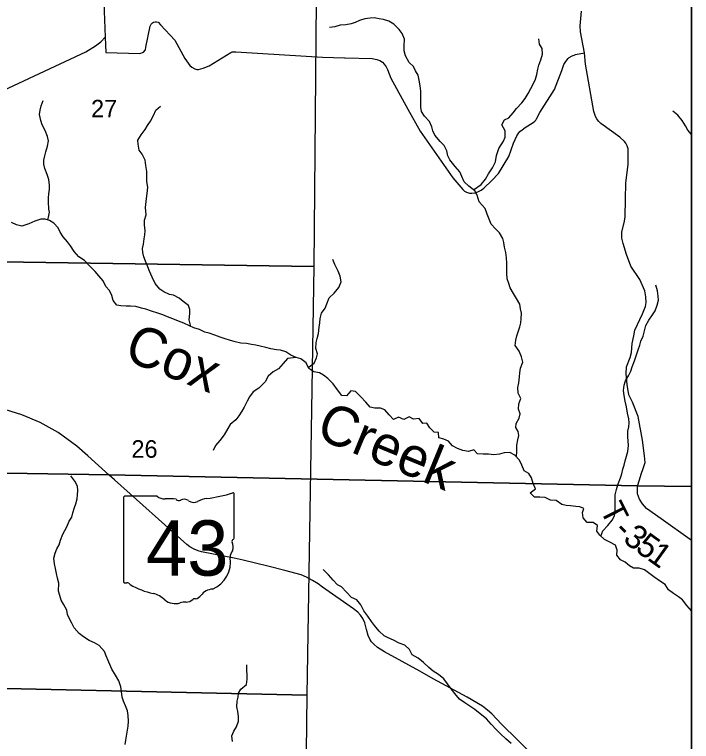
# Model space of a CAD drawing. Extents: x -3.6 to 34, y 0 to 32.8.
# Drawn here: x 1.556 to 3.17, y 29.85 to 31.583 of the extents above; entities that cross this region are included whole.
import ezdxf

# ---------------------------------------------------------------- set-up
doc = ezdxf.new("R2010")
doc.units = 0
for name, color, linetype in [('GM_X_Corporation', 7, 'Continuous'), ('GM_X_Minor_River', 7, 'Continuous'), ('GM_X_Minor_River_Text', 7, 'Continuous'), ('GM_X_Section_Text', 7, 'Continuous'), ('GM_X_State_Location', 7, 'Continuous'), ('GM_X_State_Route', 7, 'Continuous'), ('GM_X_State_Shield', 7, 'Continuous'), ('GM_X_Township_Road', 7, 'Continuous'), ('GM_X_Township_Road_Text', 7, 'Continuous'), ('SH_Data', 7, 'Continuous')]:
    doc.layers.add(name, color=color, linetype=linetype)

msp = doc.modelspace()

# ---------------------------------------------------------------- linework, layer by layer
at = {"layer": 'GM_X_Corporation'}
for points in [[(3.1705, 28.9337), (3.1705, 32.8429), (-3.6295, 32.8429), (-3.6295, 26.0429), (2.3706, 26.0429), (2.3712, 26.0804), (2.3716, 26.1248), (2.3732, 26.2253), (2.3789, 26.6097), (2.3911, 27.5117), (2.3952, 27.9336), (2.3997, 28.282), (2.4082, 28.9473), (2.5416, 28.945), (2.5837, 28.9442), (2.8343, 28.9397)], [(3.1705, 30.458), (3.1705, 32.8429), (-3.6295, 32.8429), (-3.6295, 30.6462), (-3.5736, 30.6453), (-2.8007, 30.6338), (-2.7027, 30.634), (-2.3541, 30.6318), (-0.5034, 30.5954), (-0.453, 30.5952), (-0.398, 30.5946), (0.2583, 30.5905), (0.2578, 30.5133), (0.3556, 30.5115), (0.4055, 30.5105), (1.2437, 30.4948), (1.7819, 30.4857), (3.0419, 30.4594)], [(1.2712, 32.0083), (2.2789, 31.9792), (2.27, 30.9827), (1.2573, 30.9978)], [(1.2573, 30.9978), (2.27, 30.9827), (2.2535, 29.9602), (1.2483, 29.9822)], [(2.2535, 29.9602), (2.2411, 28.9502), (1.4051, 28.9619), (1.2386, 28.9647), (1.2483, 29.9822)]]:
    msp.add_lwpolyline(points, close=True, dxfattribs=at)
msp.add_lwpolyline([(-2.8635, 26.0429), (2.3706, 26.0429), (2.3712, 26.0804), (2.3716, 26.1248), (2.3732, 26.2253), (2.3789, 26.6097), (2.3911, 27.5117), (2.3952, 27.9336), (2.3997, 28.282), (2.4082, 28.9473), (2.5416, 28.945), (2.5837, 28.9442), (2.8343, 28.9397), (3.1705, 28.9337), (3.1705, 30.458), (3.0419, 30.4594), (1.7819, 30.4857), (1.2437, 30.4948), (0.4055, 30.5105), (0.3556, 30.5115), (0.2578, 30.5133), (0.2583, 30.5905), (-0.398, 30.5946), (-0.453, 30.5952)], dxfattribs=at)
at = {"layer": 'GM_X_Minor_River'}
for points in [[(2.6645, 31.1367), (2.6593, 31.1528), (2.6538, 31.163), (2.6399, 31.1741), (2.6284, 31.1849), (2.6225, 31.1974), (2.6181, 31.2083), (2.6069, 31.221), (2.5941, 31.2367), (2.5897, 31.2469), (2.5873, 31.2583), (2.5806, 31.2714), (2.5709, 31.2811), (2.5585, 31.2961), (2.5538, 31.3059), (2.5514, 31.3157), (2.5459, 31.3282), (2.5335, 31.3412), (2.5265, 31.3521), (2.5251, 31.3627), (2.5249, 31.3779), (2.5251, 31.3908), (2.5249, 31.401), (2.5235, 31.4135), (2.5214, 31.4272), (2.5189, 31.4389), (2.5123, 31.4494), (2.5076, 31.4592), (2.4975, 31.4693), (2.4886, 31.4847), (2.4857, 31.4968), (2.4855, 31.5089), (2.4864, 31.5249), (2.4808, 31.5381), (2.4734, 31.5482), (2.4607, 31.5605), (2.4488, 31.5679), (2.4358, 31.5719), (2.4256, 31.5736), (2.4141, 31.5753), (2.4046, 31.5751), (2.3914, 31.5734), (2.3785, 31.5694), (2.3688, 31.5643), (2.3586, 31.5615), (2.3461, 31.559), (2.3328, 31.5581), (2.3203, 31.5544), (2.3074, 31.5527)], [(2.6505, 31.1656), (2.6691, 31.178), (2.6795, 31.1911), (2.6861, 31.2037), (2.6958, 31.2183), (2.7031, 31.2324), (2.7059, 31.2477), (2.711, 31.2637), (2.7224, 31.2813), (2.7264, 31.2909), (2.7262, 31.3064), (2.718, 31.3207), (2.725, 31.3322), (2.7348, 31.3369), (2.7452, 31.3488), (2.753, 31.3592), (2.7661, 31.3731), (2.7739, 31.3834), (2.7813, 31.3953), (2.7871, 31.4072), (2.7927, 31.4175), (2.7982, 31.4294), (2.8014, 31.4404), (2.8038, 31.4534), (2.8063, 31.4629), (2.8111, 31.4751), (2.815, 31.4892), (2.8144, 31.5029), (2.8081, 31.513), (2.8064, 31.5255)], [(1.6381, 31.1192), (1.6371, 31.1365), (1.6373, 31.1464), (1.6383, 31.1559), (1.6392, 31.1669), (1.6398, 31.1768), (1.6377, 31.19), (1.6341, 31.2021), (1.6285, 31.2161), (1.6261, 31.2263), (1.6263, 31.2365), (1.6288, 31.2464), (1.6309, 31.2559), (1.6352, 31.2693), (1.6369, 31.2826), (1.6352, 31.2928), (1.6293, 31.3071), (1.6222, 31.3207), (1.6186, 31.3305), (1.6161, 31.3452), (1.6171, 31.3551), (1.6196, 31.3654), (1.6243, 31.3784)], [(1.8685, 31.1231), (1.8712, 31.1449), (1.8725, 31.1571), (1.8742, 31.1716), (1.872, 31.1852), (1.8718, 31.1973), (1.872, 31.2095), (1.8695, 31.2231), (1.8678, 31.2359), (1.8603, 31.2502), (1.8537, 31.2604), (1.8508, 31.274), (1.8503, 31.2838), (1.8584, 31.2965), (1.8681, 31.3096), (1.8736, 31.3191), (1.8803, 31.3291), (1.8876, 31.3425), (1.8935, 31.3551), (1.9039, 31.3652)], [(3.1705, 31.2978), (3.162, 31.3074), (3.1565, 31.3183), (3.1487, 31.3311), (3.1379, 31.3435), (3.1263, 31.3531)], [(2.7531, 30.5281), (2.7538, 30.5434), (2.7543, 30.5563), (2.7564, 30.5696), (2.7585, 30.5795), (2.7576, 30.589), (2.7518, 30.5988), (2.7524, 30.6083), (2.7594, 30.6209), (2.7619, 30.6316), (2.7579, 30.6421), (2.7592, 30.6547), (2.7636, 30.668), (2.7573, 30.6808), (2.7567, 30.6944), (2.7589, 30.7051), (2.7602, 30.7191), (2.7615, 30.7294), (2.7629, 30.74), (2.7683, 30.7545), (2.7655, 30.7674), (2.7596, 30.781), (2.7499, 30.7945), (2.7516, 30.807), (2.7537, 30.8169), (2.7574, 30.8268), (2.7614, 30.8386), (2.7635, 30.8485), (2.7645, 30.858), (2.765, 30.8713), (2.763, 30.8815), (2.7609, 30.8925), (2.7531, 30.906), (2.7461, 30.9184), (2.7384, 30.9316), (2.7352, 30.9418), (2.7312, 30.9535), (2.7303, 30.9664), (2.7305, 30.9766), (2.7299, 30.9907), (2.7293, 31.0035), (2.7276, 31.0157), (2.7244, 31.0289), (2.7227, 31.0395), (2.7203, 31.0497), (2.7125, 31.0628), (2.7029, 31.0722), (2.6929, 31.0838), (2.6882, 31.0955), (2.6835, 31.1075), (2.6783, 31.1208), (2.6645, 31.1367)], [(1.6356, 31.0938), (1.6369, 31.1003), (1.6394, 31.1121), (1.6381, 31.1192)], [(1.9764, 30.8399), (1.9729, 30.8558), (1.9742, 30.8702), (1.974, 30.8797), (1.9708, 30.8895), (1.9586, 30.8995), (1.949, 30.9074), (1.9353, 30.914), (1.9254, 30.9157), (1.9124, 30.9224), (1.9029, 30.9283), (1.8917, 30.9422), (1.8847, 30.9568), (1.878, 30.9715), (1.8737, 30.9817), (1.8682, 30.9957), (1.8646, 31.0059), (1.8622, 31.0157), (1.8617, 31.0259), (1.8634, 31.0362), (1.8655, 31.0484), (1.8669, 31.0582), (1.8675, 31.0677), (1.8661, 31.0817), (1.8663, 31.0931), (1.8699, 31.1061), (1.8685, 31.1231)], [(2.2282, 30.7659), (2.2148, 30.7714), (2.203, 30.7792), (2.1908, 30.7828), (2.1813, 30.7838), (2.1673, 30.7866), (2.1551, 30.7891), (2.1419, 30.7927), (2.132, 30.7948), (2.1214, 30.7965), (2.1092, 30.7986), (2.096, 30.7996), (2.0827, 30.8032), (2.069, 30.8071), (2.0583, 30.81), (2.0469, 30.814), (2.034, 30.8187), (2.0207, 30.8235), (2.01, 30.8264), (1.9971, 30.8322), (1.9841, 30.8366), (1.9731, 30.8414), (1.9601, 30.8472), (1.9476, 30.8523), (1.9339, 30.8575), (1.9209, 30.8629), (1.9099, 30.8677), (1.8981, 30.871), (1.8829, 30.8764), (1.8696, 30.8808), (1.8593, 30.8836), (1.8456, 30.8869), (1.8328, 30.8878), (1.8225, 30.8884), (1.8097, 30.889), (1.8002, 30.8903), (1.7917, 30.9012), (1.7885, 30.9137), (1.7826, 30.925), (1.7741, 30.9347), (1.7679, 30.9486), (1.7575, 30.9606), (1.7482, 30.9703), (1.7359, 30.9838), (1.7229, 30.9969), (1.7095, 31.0058), (1.6983, 31.0181), (1.6894, 31.0317), (1.6825, 31.0414), (1.6724, 31.0534), (1.6647, 31.0647), (1.6604, 31.0745), (1.6496, 31.0861), (1.6393, 31.0927), (1.629, 31.0956), (1.6192, 31.0955), (1.6045, 31.0907), (1.5902, 31.084), (1.5737, 31.0788), (1.5607, 31.0821), (1.5489, 31.0876)], [(2.2566, 30.7416), (2.2704, 30.7517), (2.2762, 30.7647), (2.2784, 30.7742), (2.2751, 30.7874), (2.2753, 30.8015), (2.2782, 30.811), (2.281, 30.8228), (2.2827, 30.838), (2.284, 30.8486), (2.285, 30.8585), (2.2886, 30.8715), (2.2971, 30.883), (2.3008, 30.8936), (2.3066, 30.9081), (2.3185, 30.9189), (2.3293, 30.9324), (2.3348, 30.9461), (2.3327, 30.9597), (2.3283, 30.9718), (2.3201, 30.9872), (2.315, 30.9993)], [(2.9541, 30.3397), (2.9595, 30.3519), (2.971, 30.365), (2.9814, 30.378), (2.987, 30.388), (2.9887, 30.3998), (2.9883, 30.4248), (2.9888, 30.4377), (2.9917, 30.451), (2.9956, 30.4644), (3.0011, 30.4785), (3.0047, 30.4884), (3.0072, 30.499), (3.0097, 30.5089), (3.0122, 30.5192), (3.0158, 30.5303), (3.0187, 30.5413), (3.0203, 30.5554), (3.0198, 30.566), (3.0189, 30.5766), (3.0187, 30.5899), (3.0208, 30.6001), (3.0222, 30.6096), (3.0209, 30.6195), (3.018, 30.6327), (3.0152, 30.6478), (3.0123, 30.6618), (3.0098, 30.6747), (3.0081, 30.6868), (3.0098, 30.6993), (3.0134, 30.71), (3.0208, 30.7234), (3.0256, 30.733), (3.0292, 30.7436), (3.0343, 30.7574), (3.0405, 30.7741), (3.0434, 30.7837), (3.047, 30.7947), (3.0498, 30.8043), (3.055, 30.8168), (3.0589, 30.8321), (3.0614, 30.842), (3.0688, 30.8546), (3.0773, 30.8672), (3.0836, 30.8768), (3.089, 30.8902), (3.0915, 30.9024), (3.091, 30.9118), (3.0896, 30.9247), (3.0856, 30.9379)], [(2.2282, 30.7659), (2.2074, 30.7629), (2.197, 30.751), (2.1854, 30.7387), (2.1731, 30.7313), (2.1607, 30.7213), (2.1537, 30.7079), (2.1385, 30.6921), (2.125, 30.6836), (2.1168, 30.6717), (2.1113, 30.6614), (2.104, 30.6468), (2.0984, 30.6373), (2.091, 30.6265), (2.0836, 30.6166), (2.0702, 30.6061), (2.0646, 30.5962), (2.0562, 30.5809), (2.0454, 30.5678), (2.0354, 30.5555), (2.0299, 30.5437)], [(3.1705, 30.1613), (3.1594, 30.174), (3.1493, 30.1875), (3.1398, 30.1946), (3.1279, 30.2024), (3.116, 30.2117), (3.1079, 30.224), (3.0945, 30.233), (3.0811, 30.2426), (3.0681, 30.2519), (3.0586, 30.259), (3.0456, 30.2633), (3.0324, 30.2635), (3.0228, 30.2687), (3.0121, 30.2776), (3.0014, 30.2831), (2.9922, 30.2944), (2.9931, 30.3065), (2.9892, 30.3182), (2.9762, 30.3252), (2.9632, 30.3315), (2.9521, 30.3416), (2.9448, 30.3513), (2.9464, 30.365), (2.9361, 30.3724), (2.9217, 30.3722), (2.9125, 30.3835), (2.9108, 30.3956), (2.914, 30.4051), (2.9045, 30.4095), (2.8947, 30.4101), (2.8818, 30.4118), (2.8719, 30.4124), (2.8613, 30.4153), (2.8475, 30.4242), (2.8346, 30.4255), (2.8213, 30.4314), (2.8092, 30.4327), (2.7959, 30.4326), (2.7859, 30.443), (2.7983, 30.4527), (2.7932, 30.4651), (2.7892, 30.4783), (2.7826, 30.4893), (2.7719, 30.4952), (2.7656, 30.5087), (2.7605, 30.5204), (2.749, 30.5324), (2.7372, 30.539), (2.7239, 30.5381), (2.713, 30.5349), (2.6994, 30.5332), (2.6861, 30.5349), (2.6737, 30.535), (2.6604, 30.5356), (2.6512, 30.5457), (2.6384, 30.5417), (2.6251, 30.5442), (2.6129, 30.5486), (2.6007, 30.5548), (2.5911, 30.5661), (2.58, 30.5708), (2.5679, 30.5744), (2.5673, 30.587), (2.5571, 30.5879), (2.5467, 30.5976), (2.5397, 30.6089), (2.5295, 30.6084), (2.5214, 30.6204), (2.5074, 30.6183), (2.4971, 30.6238), (2.4843, 30.618), (2.4718, 30.6235), (2.4597, 30.6176), (2.4497, 30.6292), (2.439, 30.6404), (2.4291, 30.6445), (2.4154, 30.645), (2.404, 30.6475), (2.3936, 30.6591), (2.3821, 30.6718), (2.3694, 30.6842), (2.358, 30.6859), (2.3476, 30.674), (2.337, 30.675), (2.3262, 30.6881), (2.3158, 30.7027), (2.3035, 30.7158), (2.2931, 30.7236), (2.2836, 30.7288), (2.2703, 30.7312), (2.2577, 30.7394), (2.2514, 30.7526), (2.2388, 30.7623), (2.2282, 30.7659)], [(1.8203, 29.843), (1.8217, 29.8533), (1.8241, 29.867), (1.8259, 29.8765), (1.8272, 29.886), (1.8278, 29.8985), (1.8272, 29.9121), (1.8252, 29.9227), (1.8212, 29.9352), (1.8161, 29.9461), (1.8129, 29.9559), (1.8112, 29.9688), (1.8095, 29.9805), (1.8052, 29.9945), (1.797, 30.0084), (1.7885, 30.0223), (1.7837, 30.0336), (1.779, 30.0442), (1.7751, 30.0544), (1.7704, 30.0641), (1.7581, 30.0784), (1.747, 30.085), (1.7341, 30.0909), (1.7203, 30.0994), (1.71, 30.1076), (1.6988, 30.1211), (1.6926, 30.1324), (1.6875, 30.1425), (1.6828, 30.1523), (1.6807, 30.1629), (1.6733, 30.1772), (1.6671, 30.187), (1.6639, 30.1983), (1.6611, 30.2081), (1.6616, 30.2271), (1.6588, 30.2396), (1.6559, 30.2502), (1.6535, 30.2627), (1.6518, 30.2732), (1.6501, 30.2873), (1.6529, 30.2991), (1.6573, 30.3094), (1.6628, 30.3189), (1.6661, 30.33), (1.6712, 30.3445), (1.6811, 30.3621), (1.6866, 30.375), (1.6925, 30.385), (1.6954, 30.3953), (1.6993, 30.4075), (1.7026, 30.417), (1.7054, 30.4284), (1.7064, 30.4383), (1.707, 30.4482), (1.7065, 30.4584), (1.6999, 30.4705), (1.6902, 30.4836)], [(2.7402, 29.8453), (2.7275, 29.8561), (2.7152, 29.8685), (2.7045, 29.8786), (2.6929, 29.8913), (2.6818, 29.9036), (2.6668, 29.9159), (2.6542, 29.926), (2.6416, 29.9341), (2.6301, 29.9419), (2.6175, 29.9505), (2.6059, 29.964), (2.5971, 29.9752), (2.5889, 29.9872), (2.58, 29.9996), (2.5674, 30.0093), (2.5544, 30.0178), (2.5444, 30.0264), (2.5318, 30.0383), (2.5191, 30.0484), (2.5046, 30.0565), (2.4984, 30.0689), (2.4873, 30.0794), (2.4732, 30.0841), (2.4602, 30.0915), (2.4473, 30.097), (2.4377, 30.1022), (2.4258, 30.113), (2.415, 30.1261), (2.4077, 30.1363), (2.3984, 30.1486), (2.3895, 30.1618), (2.3817, 30.1757), (2.3721, 30.1873), (2.3599, 30.1936), (2.3476, 30.2063), (2.336, 30.2183), (2.3265, 30.2238), (2.3161, 30.2343), (2.3053, 30.247), (2.2919, 30.2601)], [(2.0757, 29.8495), (2.0743, 29.8631), (2.0794, 29.8742), (2.0853, 29.8845), (2.09, 29.8986), (2.0906, 29.9096), (2.0886, 29.921), (2.0861, 29.9327), (2.0874, 29.946), (2.0892, 29.9555), (2.0905, 29.965), (2.0961, 29.9746), (2.1091, 29.9858), (2.1108, 29.9983), (2.1107, 30.0078), (2.1101, 30.0199), (2.1099, 30.0324)]]:
    msp.add_lwpolyline(points, dxfattribs=at)
at = {"layer": 'GM_X_State_Route'}
msp.add_lwpolyline([(2.8077, 29.8013), (2.7556, 29.8537), (2.7177, 29.8914), (2.6943, 29.9157), (2.6844, 29.9245), (2.6722, 29.9337), (2.6354, 29.9555), (2.5542, 29.9992), (2.523, 30.0172), (2.4382, 30.0637), (2.4217, 30.0742), (2.4128, 30.0823), (2.4076, 30.0872), (2.4035, 30.0937), (2.3992, 30.1026), (2.3955, 30.1173), (2.3913, 30.133), (2.3866, 30.1428), (2.3809, 30.1512), (2.3745, 30.1581), (2.3644, 30.166), (2.291, 30.2178), (2.2802, 30.2257), (2.2668, 30.2337), (2.2523, 30.2417), (2.2397, 30.2469), (2.2008, 30.2576), (2.16, 30.2678), (2.1018, 30.2824), (2.0799, 30.2871), (2.0017, 30.3024), (1.9943, 30.3045), (1.9846, 30.3083), (1.9745, 30.3144), (1.9674, 30.3199), (1.7949, 30.4735), (1.7821, 30.4851), (1.7309, 30.5313), (1.7051, 30.5542), (1.6604, 30.5865), (1.6176, 30.6104), (1.5736, 30.6285), (1.5197, 30.6456)], dxfattribs=at)
at = {"layer": 'GM_X_State_Shield'}
for p, q in [((1.8163, 30.4314), (1.8163, 30.2313)), ((1.8961, 30.4348), (1.8189, 30.4348)), ((2.08, 30.3351), (2.08, 30.4398)), ((2.08, 30.3351), (2.08, 30.3351))]:
    msp.add_line(p, q, dxfattribs=at)
for centre, radius, start, end in [((1.9861, 30.7077), 0.2796, 275.8445, 288.9065), ((2.0771, 30.4402), 0.00294, 351.8621, 97.738), ((1.8193, 30.4318), 0.00305, 98.1301, 188.1301), ((1.9145, 30.4581), 0.0296, 231.6195, 271.1119), ((1.9243, 30.3225), 0.1064, 80.4867, 94.9883), ((1.9485, 30.4328), 0.00855, 219.7921, 297.1024), ((1.961, 30.4097), 0.0178, 54.4667, 119.1411), ((2.0217, 30.3737), 0.0563, 97.3462, 120.7689), ((1.984, 30.4414), 0.0214, 233.8562, 294.8282), ((2.0793, 30.3274), 0.00454, 107.944, 210.337), ((2.0504, 30.3142), 0.0273, 340.033, 23.6496), ((2.0768, 30.3347), 0.00314, 289.6038, 7.7341), ((2.0905, 30.2913), 0.0198, 136.8065, 186.9296), ((2.0017, 30.278), 0.0699, 292.3089, 8.9858), ((1.8194, 30.2308), 0.00308, 171.9584, 258.3066), ((1.8198, 30.2513), 0.0235, 267.339, 280.6039), ((1.8246, 30.2197), 0.00848, 29.7484, 93.2717), ((1.9317, 30.3995), 0.2019, 240.4129, 257.1985), ((1.8715, 30.1414), 0.0632, 47.1842, 75.836), ((2.0312, 30.1751), 0.0383, 94.4031, 142.5768), ((1.9398, 30.2187), 0.0401, 230.7004, 286.2918), ((1.963, 30.1495), 0.0329, 85.6951, 111.2099), ((1.9659, 30.2037), 0.0214, 268.777, 315.5493), ((1.9852, 30.1844), 0.00601, 65.7517, 132.6484), ((1.9827, 30.2119), 0.0226, 282.8732, 323.2771)]:
    msp.add_arc(centre, radius, start, end, dxfattribs=at)
at = {"layer": 'GM_X_Township_Road'}
for points in [[(1.7647, 31.7372), (1.7726, 31.5296)], [(2.9153, 31.4922), (2.9057, 31.5425), (2.9049, 31.5569), (2.9079, 31.5917)], [(1.7726, 31.5296), (1.774, 31.4926), (1.8548, 31.4904), (1.8635, 31.4936), (1.8683, 31.4991), (1.8691, 31.5053), (1.8799, 31.556), (1.8822, 31.5607), (1.8852, 31.5639), (1.8879, 31.5652), (1.8916, 31.5663), (1.8949, 31.5663), (1.8984, 31.5656), (1.9044, 31.5588), (1.9388, 31.5223), (1.9621, 31.4789), (1.9746, 31.462), (1.9793, 31.4577), (1.9858, 31.4539), (1.9907, 31.4528), (1.9953, 31.4522), (2.0063, 31.4554), (2.0203, 31.4614), (2.0723, 31.4933), (2.0752, 31.4945), (2.0776, 31.4949), (2.0843, 31.4949), (2.0965, 31.4937), (2.2909, 31.4815), (2.343, 31.4802), (2.3443, 31.4801)], [(1.4549, 31.3678), (1.726, 31.4948), (1.7493, 31.5087), (1.7616, 31.5182), (1.7726, 31.5296)], [(2.3443, 31.4801), (2.4094, 31.4785), (2.4202, 31.4766), (2.4273, 31.4739), (2.4339, 31.4697), (2.4378, 31.4654), (2.4423, 31.4584), (2.4457, 31.4522), (2.4537, 31.4315), (2.4944, 31.3577), (2.5232, 31.3055), (2.6015, 31.1941), (2.6252, 31.1659), (2.6292, 31.162), (2.6341, 31.1597), (2.6415, 31.1576), (2.6468, 31.1574), (2.6545, 31.1584), (2.6608, 31.1607), (2.6687, 31.1647), (2.6755, 31.1697), (2.6943, 31.1875), (2.7102, 31.2046), (2.7349, 31.245), (2.7464, 31.2771), (2.7541, 31.294), (2.7587, 31.3012), (2.7615, 31.3044), (2.7665, 31.3087), (2.7739, 31.3142), (2.793, 31.3263), (2.7968, 31.329), (2.7991, 31.3316), (2.8009, 31.3344), (2.8089, 31.3502), (2.844, 31.4048), (2.8614, 31.4504), (2.8665, 31.4642), (2.8707, 31.4714), (2.8735, 31.475), (2.8764, 31.4783), (2.8791, 31.4808), (2.8862, 31.4848), (2.8905, 31.4867), (2.8941, 31.4883), (2.9153, 31.4922)], [(3.0571, 30.5059), (3.0601, 30.5152), (3.0584, 30.5308), (3.0537, 30.5686), (3.0434, 30.6248), (3.0297, 30.6592), (3.0214, 30.6762), (3.0174, 30.7009), (3.0145, 30.727), (3.0158, 30.7433), (3.0246, 30.7653), (3.0273, 30.7776), (3.0294, 30.7988), (3.0327, 30.8173), (3.0358, 30.8305), (3.0536, 30.8699), (3.0572, 30.8779), (3.0607, 30.8872), (3.0622, 30.897), (3.0619, 30.9101), (3.0592, 30.9248), (3.0472, 30.9517), (3.0258, 30.9838), (3.0158, 31.0111), (3.0076, 31.0374), (3.0045, 31.05), (3.0041, 31.0643), (3.0104, 31.0907), (3.0125, 31.1009), (3.0129, 31.1434), (3.0143, 31.1817), (3.0196, 31.2269), (3.0196, 31.2552), (3.0194, 31.2635), (3.0175, 31.2707), (3.0138, 31.2768), (3.0107, 31.2806), (3, 31.2907), (2.9541, 31.3239), (2.9486, 31.3289), (2.9445, 31.3347), (2.9414, 31.3405), (2.9374, 31.3525), (2.9181, 31.4649), (2.9153, 31.4922)], [(3.1705, 30.3294), (3.1677, 30.3315), (3.0983, 30.3812), (3.0632, 30.4058), (3.0541, 30.417), (3.0468, 30.4276), (3.0419, 30.4401), (3.0421, 30.4589), (3.0462, 30.4735), (3.0505, 30.4871), (3.0556, 30.5012), (3.0571, 30.5059)]]:
    msp.add_lwpolyline(points, dxfattribs=at)
at = {"layer": 'SH_Data'}
msp.add_line((3.1705, 32.8429), (3.1705, 26.0429), dxfattribs=at)

# ---------------------------------------------------------------- texts
at = {"layer": 'GM_X_Minor_River_Text'}
for s, height, rotation, p in [('Cox', 0.09471, 338.6608, (1.8135, 30.7617)), ('Creek', 0.09472, 337.6513, (2.2711, 30.5755))]:
    msp.add_text(s, height=height, rotation=rotation, dxfattribs=at).set_placement(p)
at = {"layer": 'GM_X_Section_Text'}
for s, p in [('27', (1.7387, 31.3382)), ('26', (1.835, 30.5265))]:
    msp.add_text(s, height=0.04186, rotation=0, dxfattribs=at).set_placement(p)
at = {"layer": 'GM_X_State_Location'}
msp.add_text('43', height=0.000189, rotation=0, dxfattribs=at).set_placement((1.8975, 30.3042))
for s in ['s', 'r']:
    msp.add_text(s, height=0.000189, dxfattribs=at).set_placement((1.9452, 30.318))
at = {"layer": 'GM_X_State_Shield'}
msp.add_text('43', height=0.13184, dxfattribs=at).set_placement((1.87, 30.2454))
at = {"layer": 'GM_X_Township_Road_Text'}
for s, rotation, p in [('T', 296.7903, (2.9512, 30.4034)), ('-', 315.7119, (2.9824, 30.349)), ('3', 322.4037, (3.0046, 30.328)), ('5', 324.2363, (3.0339, 30.3055)), ('1', 324.3638, (3.0624, 30.2849))]:
    msp.add_text(s, height=0.0568, rotation=rotation, dxfattribs=at).set_placement(p)

doc.saveas('drawing.dxf')
